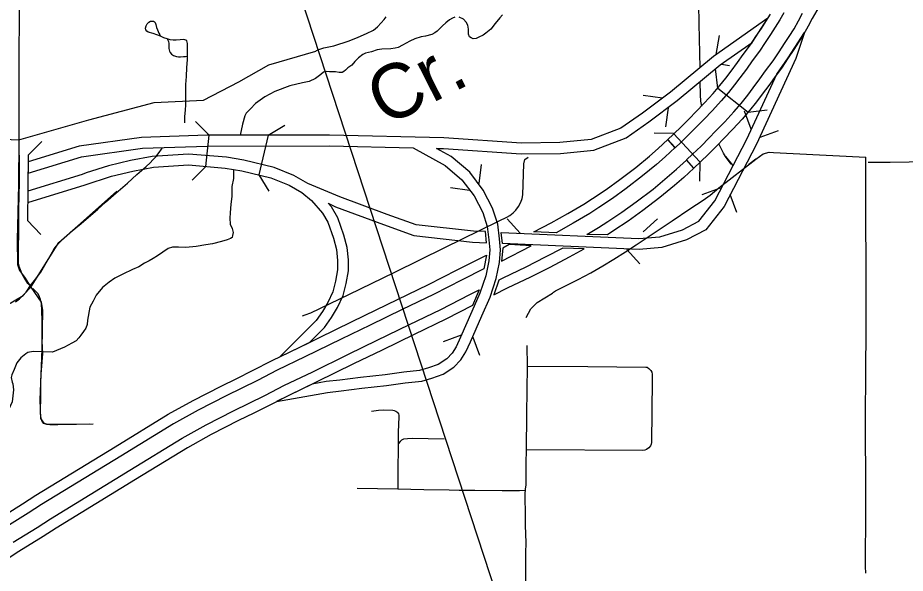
# Model space of a CAD drawing. Extents: x 670147 to 673275, y 705573 to 707613.
# Drawn here: x 671613.5 to 671751.4, y 706162.9 to 706249.1 of the extents above; entities that cross this region are included whole.
import ezdxf

# ---------------------------------------------------------------- set-up
doc = ezdxf.new("R2010")
doc.units = 0
for name, color, linetype in [('10', 7, 'Continuous'), ('19', 7, 'Continuous'), ('31', 7, 'Continuous'), ('32', 7, 'Continuous'), ('33', 7, 'Continuous'), ('34', 7, 'Continuous'), ('35', 7, 'Continuous'), ('38', 7, 'Continuous'), ('39', 7, 'Continuous'), ('45', 7, 'Continuous'), ('6', 7, 'Continuous'), ('Default', 7, 'Continuous')]:
    doc.layers.add(name, color=color, linetype=linetype)

msp = doc.modelspace()

# ---------------------------------------------------------------- linework, layer by layer
at = {"layer": '10'}
for points in [[(671727.63, 706245.26), (671730.09, 706249.03), (671721.63, 706243.12), (671714.96, 706237.58), (671710.59, 706234.32), (671707.26, 706231.99), (671702.65, 706230.22), (671697.78, 706229.73), (671691.81, 706229.67), (671679.74, 706230.49), (671661.98, 706230.9), (671642.96, 706230.88), (671632.75, 706230.55), (671623.07, 706229.18)], [(671688.83, 706214.08), (671688.66, 706215.78), (671710.05, 706214.84), (671713.29, 706215.13), (671716.82, 706216.21), (671719.35, 706217.53), (671721.86, 706220.71), (671726.83, 706230.25), (671731.47, 706240.35), (671733.25, 706242.89), (671735.79, 706246.82)], [(671735.79, 706246.82), (671734.45, 706242.81), (671728.34, 706229.51), (671723.27, 706219.79), (671720.45, 706216.2), (671717.45, 706214.65), (671713.61, 706213.47), (671710.09, 706213.15), (671688.83, 706214.08)], [(671678.62, 706228.83), (671679.66, 706228.81), (671691.76, 706227.99), (671697.87, 706228.05), (671703.04, 706228.58), (671708.06, 706230.5), (671711.57, 706232.96), (671716, 706236.26), (671722.65, 706241.79), (671727.63, 706245.26)], [(671623.07, 706229.18), (671615.15, 706226.75), (671615.13, 706224.98)], [(671623.44, 706227.53), (671632.9, 706228.88), (671642.98, 706229.2), (671661.97, 706229.22), (671674.98, 706228.92)], [(671674.98, 706228.92), (671679.92, 706226.2), (671682.54, 706223.97), (671684.43, 706221.46), (671685.77, 706218.89), (671686.48, 706216.7), (671686.71, 706214.62), (671686.87, 706213.07), (671686.71, 706211.38), (671686.26, 706209.07), (671685.35, 706206.35), (671684.08, 706203.51), (671682.33, 706199.51), (671681.66, 706198.04), (671681.03, 706197.05), (671680.21, 706196.18), (671678.86, 706195.3), (671677.34, 706194.75), (671675.97, 706194.37), (671673.51, 706194.08), (671670.64, 706193.67), (671666.78, 706193.26), (671663.56, 706192.85), (671661.44, 706192.62), (671659.29, 706192.24), (671653.73, 706189.55)], [(671653.73, 706189.55), (671661.67, 706190.95), (671663.76, 706191.19), (671666.98, 706191.6), (671670.85, 706192.01), (671673.72, 706192.42), (671676.29, 706192.72), (671677.85, 706193.15), (671679.61, 706193.78), (671681.3, 706194.89), (671682.36, 706196.01), (671683.13, 706197.24), (671683.86, 706198.82), (671685.62, 706202.83), (671686.92, 706205.74), (671687.89, 706208.64), (671688.37, 706211.13), (671688.56, 706213.07), (671688.38, 706214.8), (671688.13, 706217.05), (671687.32, 706219.55), (671685.85, 706222.36), (671683.77, 706225.13), (671680.88, 706227.59), (671678.62, 706228.83)], [(671615.13, 706224.98), (671623.44, 706227.53)], [(671658.62, 706223.39), (671656.43, 706224.63), (671653.38, 706225.88), (671648.67, 706227), (671645.97, 706227.45), (671640.08, 706227.96), (671634.39, 706227.57), (671631.04, 706226.95), (671627.65, 706226.14), (671624.14, 706225.02), (671623.51, 706224.79)], [(671624, 706223.19), (671628.1, 706224.52), (671631.39, 706225.31), (671634.6, 706225.9), (671640.07, 706226.27), (671645.76, 706225.78), (671648.34, 706225.36), (671652.86, 706224.27), (671655.7, 706223.11), (671657.66, 706222.01), (671659.19, 706220.73), (671660.9, 706218.76), (671661.72, 706217.36), (671662.59, 706214.89), (671663.06, 706213.14), (671663.22, 706211.44), (671663.23, 706209.97), (671662.92, 706208.23), (671662.51, 706206.57), (671661.72, 706204.9), (671660.9, 706203.5), (671659.89, 706202.11), (671654.24, 706196.46)], [(671623.51, 706224.79), (671615.09, 706222.21), (671615.07, 706220.44)], [(671615.07, 706220.44), (671624, 706223.19)], [(671686.38, 706214.19), (671686.23, 706215.92), (671684.32, 706215.96), (671675.43, 706216.97), (671670.92, 706218.58), (671663.58, 706221.33), (671658.62, 706223.39)], [(671654.24, 706196.46), (671658.85, 706198.7), (671661.17, 706201.02), (671662.3, 706202.58), (671663.21, 706204.12), (671664.1, 706206), (671664.56, 706207.88), (671664.91, 706209.83), (671664.9, 706211.53), (671664.72, 706213.44), (671664.19, 706215.38), (671663.25, 706218.07), (671662.27, 706219.74), (671661.75, 706220.34)], [(671661.75, 706220.34), (671662.92, 706219.78), (671670.34, 706217), (671675.05, 706215.32), (671684.19, 706214.29), (671686.38, 706214.19)]]:
    msp.add_lwpolyline(points, dxfattribs=at)
at = {"layer": '19'}
for p, q in [((671714.55, 706230.2), (671714.49, 706230.16)), ((671718.61, 706225.8), (671718.59, 706225.77))]:
    msp.add_line(p, q, dxfattribs=at)
for points in [[(671738.41, 706251.51), (671736.98, 706249), (671736.36, 706247.81), (671735.61, 706246.52), (671734.82, 706245.31), (671734.11, 706244.18), (671733.25, 706242.89), (671732.31, 706241.46), (671731.1, 706239.86), (671730.22, 706238.62), (671729.18, 706237.23), (671728.31, 706236.07), (671727.25, 706234.73), (671726.07, 706233.39), (671724.64, 706231.8), (671723.18, 706230.3), (671722.2, 706229.31), (671720.9, 706227.97), (671719.55, 706226.69), (671718.61, 706225.8)], [(671714.49, 706230.16), (671715.43, 706231.05), (671716.68, 706232.24), (671717.91, 706233.5), (671718.89, 706234.5), (671720.26, 706235.9), (671721.58, 706237.37), (671722.64, 706238.58), (671723.56, 706239.74), (671724.38, 706240.82), (671725.37, 706242.16), (671726.27, 706243.41), (671727.4, 706244.92), (671728.24, 706246.19), (671729.07, 706247.45), (671729.78, 706248.56), (671730.5, 706249.67)], [(671732.59, 706249.88), (671731.95, 706248.78), (671731.21, 706247.64), (671730.5, 706246.52), (671729.66, 706245.26), (671728.79, 706243.94), (671727.64, 706242.41), (671726.74, 706241.15), (671725.74, 706239.8), (671724.91, 706238.7), (671723.95, 706237.49), (671722.85, 706236.24), (671721.5, 706234.74), (671720.11, 706233.31), (671719.12, 706232.31), (671717.87, 706231.03), (671716.6, 706229.82), (671715.66, 706228.93), (671714.55, 706230.2)], [(671718.59, 706225.77), (671717.44, 706227.04), (671718.38, 706227.93), (671719.7, 706229.18), (671720.98, 706230.5), (671721.96, 706231.49), (671723.4, 706232.96), (671724.79, 706234.52), (671725.94, 706235.82), (671726.97, 706237.11), (671727.82, 706238.25), (671728.84, 706239.62), (671729.73, 706240.87), (671730.92, 706242.44), (671731.83, 706243.83), (671732.68, 706245.11), (671733.39, 706246.23), (671734.17, 706247.41), (671734.87, 706248.63), (671735.48, 706249.81)], [(671697.19, 706215.75), (671693.72, 706215.87), (671696.41, 706217.26), (671699, 706218.71), (671701.51, 706220.19), (671702.86, 706221.08), (671704.95, 706222.47), (671707.08, 706223.99), (671709.56, 706225.89), (671711.68, 706227.64), (671713.02, 706228.81), (671714.55, 706230.2), (671715.69, 706228.95)], [(671715.69, 706228.95), (671714.15, 706227.54), (671712.78, 706226.34), (671710.62, 706224.56), (671708.09, 706222.62), (671705.92, 706221.07), (671703.8, 706219.66), (671702.41, 706218.74), (671699.85, 706217.24), (671697.19, 706215.75)], [(671705.14, 706215.39), (671701.94, 706215.45), (671703.78, 706216.54), (671705.24, 706217.49), (671707.39, 706218.93), (671709.64, 706220.53), (671712.24, 706222.53), (671714.46, 706224.36), (671715.89, 706225.6), (671717.45, 706227.03)], [(671717.45, 706227.03), (671718.59, 706225.77), (671717.02, 706224.33), (671715.56, 706223.06), (671713.29, 706221.2), (671710.65, 706219.17), (671708.36, 706217.53), (671706.17, 706216.08), (671705.14, 706215.39)], [(671698.23, 706213.36), (671695.46, 706211.93), (671692.49, 706210.42), (671688.88, 706208.71), (671688.28, 706208.4), (671687.48, 706206.1)], [(671687.48, 706206.1), (671689.63, 706207.18), (671693.23, 706208.89), (671696.24, 706210.41), (671699.25, 706211.98), (671701.55, 706213.22), (671698.23, 706213.36)], [(671688.9, 706213.37), (671688.69, 706211.33), (671693.31, 706213.71), (671689.9, 706213.89)], [(671689.9, 706213.89), (671688.9, 706213.37)], [(671610.52, 706171.33), (671614.26, 706173.64), (671616.34, 706174.97), (671628.67, 706182.52), (671636.89, 706187.55), (671640.76, 706189.7), (671645.13, 706191.94), (671647.58, 706193.13), (671650.01, 706194.33), (671653.08, 706195.9), (671657.38, 706197.98), (671663.05, 706200.76), (671667.53, 706202.93), (671672.52, 706205.36), (671677.37, 706207.7), (671681.81, 706209.97), (671686.34, 706212.24), (671685.96, 706210.15)], [(671685.96, 706210.15), (671682.58, 706208.45), (671678.13, 706206.17), (671673.26, 706203.83), (671668.27, 706201.4), (671663.79, 706199.23), (671658.13, 706196.45), (671653.84, 706194.38), (671650.77, 706192.81), (671648.32, 706191.6), (671645.89, 706190.42), (671641.56, 706188.21), (671637.74, 706186.08), (671629.56, 706181.07), (671617.24, 706173.53), (671615.17, 706172.21), (671611.43, 706169.89)], [(671612.81, 706167.69), (671616.55, 706170), (671618.62, 706171.32), (671630.92, 706178.86), (671639.06, 706183.83), (671642.79, 706185.91), (671647.05, 706188.09), (671649.47, 706189.27), (671651.94, 706190.48), (671655, 706192.05), (671659.26, 706194.11), (671664.93, 706196.9), (671669.4, 706199.06), (671674.39, 706201.49), (671679.29, 706203.84), (671683.75, 706206.13), (671685.2, 706206.86), (671684.17, 706204.44)], [(671684.17, 706204.44), (671680.04, 706202.32), (671675.13, 706199.96), (671670.14, 706197.53), (671665.68, 706195.37), (671660.01, 706192.59), (671655.76, 706190.53), (671652.7, 706188.97), (671650.21, 706187.74), (671647.81, 706186.57), (671643.59, 706184.41), (671639.91, 706182.36), (671631.8, 706177.41), (671619.52, 706169.88), (671617.46, 706168.57), (671613.72, 706166.25), (671610.72, 706164.34)]]:
    msp.add_lwpolyline(points, dxfattribs=at)
at = {"layer": '31'}
for points in [[(671657.78, 706202.83), (671658.2, 706202.99), (671659.05, 706203.28), (671664.98, 706206.17), (671672.14, 706209.63), (671679.88, 706213.45), (671685.28, 706216.08), (671688.31, 706217.57), (671689.54, 706218.15), (671690.01, 706218.44), (671690.53, 706218.84), (671690.9, 706219.24), (671691.34, 706219.79), (671691.7, 706220.48), (671691.89, 706221.06), (671691.99, 706221.65), (671692.15, 706226.44), (671692.31, 706227.1), (671692.85, 706227.49)], [(671723.5, 706227.56), (671724.59, 706226.24)]]:
    msp.add_lwpolyline(points, dxfattribs=at)
at = {"layer": '32'}
for points in [[(671613.67, 706230.15), (671613.74, 706225.48), (671613.76, 706223.62), (671613.68, 706221.39), (671613.64, 706219.53), (671613.62, 706216.22), (671613.61, 706212.87), (671613.59, 706211.03), (671613.67, 706210.55), (671613.9, 706210.01), (671614.16, 706209.37), (671614.63, 706208.51), (671614.98, 706207.98), (671615.5, 706207.54)], [(671615.5, 706207.54), (671616.14, 706208.3), (671616.67, 706208.99), (671617.11, 706209.62), (671617.73, 706210.71), (671618.49, 706212.04), (671618.91, 706212.8), (671619.19, 706213.26), (671619.52, 706213.66), (671620.05, 706214.29), (671620.49, 706214.71), (671620.93, 706215.09), (671621.74, 706215.81), (671623.37, 706217.18), (671625.95, 706219.38), (671627.14, 706220.51), (671628.38, 706221.55), (671630.6, 706223.46), (671632.02, 706224.76), (671632.76, 706225.41), (671633.46, 706226.03), (671634.1, 706226.6), (671634.54, 706227.06), (671634.96, 706227.54), (671635.5, 706228.19), (671635.84, 706228.7), (671636.02, 706228.93)], [(671613.18, 706205.01), (671613.78, 706205.47), (671614.31, 706206.02), (671614.81, 706206.53), (671615.5, 706207.54)]]:
    msp.add_lwpolyline(points, dxfattribs=at)
at = {"layer": '33'}
for points in [[(671614.61, 706335.87), (671614.53, 706329.13), (671614.47, 706320.89), (671614.35, 706312.7), (671614.26, 706305.93), (671614.22, 706299.44), (671614.1, 706290.42), (671614.06, 706283.16), (671614.03, 706277.49), (671613.97, 706271.15), (671613.85, 706261.98), (671613.77, 706252.69), (671613.68, 706239.92), (671613.68, 706230.44), (671613.67, 706230.15)], [(671719.06, 706281.88), (671719.22, 706281.25), (671719.37, 706280.51), (671719.38, 706279.99), (671719.25, 706277.24), (671719.23, 706271.14), (671719.2, 706264.43), (671719.23, 706261.89), (671719.22, 706259.04), (671719.25, 706254.43), (671719.37, 706248.16), (671719.49, 706241.35)], [(671613.67, 706230.15), (671624.58, 706233.28), (671634.73, 706235.95), (671642.39, 706236.3), (671647.9, 706239.15), (671652.53, 706241.82), (671659.82, 706243.93)], [(671719.53, 706239.19), (671719.57, 706237.13), (671719.62, 706236.17), (671719.75, 706235.38)], [(671542.03, 706230.44), (671542.38, 706230.63), (671542.62, 706230.72), (671543.01, 706230.77), (671543.48, 706230.82), (671544.19, 706230.84), (671545.68, 706230.84), (671550.29, 706230.76), (671554.88, 706230.77), (671559.51, 706230.82), (671561.24, 706230.82), (671564.77, 706230.82), (671569, 706230.82), (671571.4, 706230.76), (671574.3, 706230.75), (671578.61, 706230.72), (671582.19, 706230.67), (671588.77, 706230.65), (671591.88, 706230.59), (671599.43, 706230.52), (671610.14, 706230.3), (671613.67, 706230.15)], [(671613.67, 706230.15), (671613.66, 706223.17), (671613.46, 706214.65), (671613.51, 706210.82), (671613.79, 706209.89), (671614.55, 706208.82), (671615.56, 706207.31)], [(671724.4, 706226.4), (671723.5, 706227.56), (671723.19, 706228.08), (671722.44, 706229.55)], [(671692.55, 706202.58), (671693.23, 706203.9), (671694.23, 706204.92), (671696.61, 706206.37), (671696.79, 706206.52), (671697.06, 706206.7), (671697.72, 706207.05), (671699.04, 706207.68), (671700.62, 706208.5), (671702.58, 706209.51), (671704.43, 706210.6), (671706.16, 706211.65), (671707.94, 706212.77), (671709.63, 706213.85), (671711.93, 706215.43), (671715.2, 706217.61), (671717.96, 706219.45), (671720.01, 706220.81), (671721.11, 706221.56), (671722.47, 706222.71), (671728.24, 706227.16)], [(671728.24, 706227.16), (671727.15, 706226.34)], [(671728.24, 706227.16), (671729.33, 706227.98), (671730.29, 706228.25), (671730.96, 706228.21), (671734.03, 706228.03), (671745.32, 706227.47)], [(671745.32, 706162.87), (671745.29, 706163.19), (671745.24, 706163.61), (671745.23, 706164.09), (671745.26, 706165.15), (671745.28, 706166.64), (671745.32, 706170.06), (671745.32, 706174.86), (671745.28, 706187.31), (671745.29, 706193.75), (671745.37, 706201.14), (671745.32, 706227.47)], [(671611.58, 706204.33), (671614.39, 706206.01), (671615.68, 706207.44), (671619.91, 706214.25), (671622.87, 706216.81), (671628.91, 706222.2)], [(671691.57, 706122.65), (671692.4, 706153.43), (671692.42, 706154.32), (671692.41, 706156.63), (671692.45, 706162.75), (671692.49, 706165.97), (671692.51, 706167.65), (671692.44, 706170.27), (671692.42, 706172.2), (671692.37, 706174.58), (671692.36, 706175.02), (671692.37, 706175.35), (671692.4, 706175.71), (671692.43, 706175.95), (671692.48, 706176.3), (671692.51, 706176.54), (671692.53, 706179.95), (671692.57, 706182.04), (671692.64, 706187.59), (671692.75, 706195.04), (671692.68, 706198.24)], [(671692.75, 706195.04), (671702.12, 706194.97), (671711.13, 706194.89), (671711.32, 706194.85), (671711.61, 706194.67), (671711.89, 706194.37), (671712.03, 706194.09), (671712.09, 706193.8), (671712.1, 706192.86), (671712.02, 706183.19), (671711.97, 706182.92), (671711.86, 706182.66), (671711.59, 706182.32), (671711.23, 706182.07), (671710.95, 706181.96), (671710.65, 706181.91), (671692.57, 706182.04)], [(671679.81, 706183.69), (671674.82, 706183.78), (671674.08, 706183.75), (671673.47, 706183.69), (671673.17, 706183.51), (671672.95, 706183.32), (671672.66, 706182.98)], [(671692.4, 706175.71), (671691.51, 706175.69), (671688.8, 706175.69), (671684.56, 706175.71), (671682.13, 706175.73), (671680.57, 706175.77), (671676.61, 706175.83), (671672.61, 706175.92), (671666.27, 706176.05)]]:
    msp.add_lwpolyline(points, dxfattribs=at)
at = {"layer": '34'}
for points in [[(671659.82, 706243.93), (671659.94, 706244.02), (671660.46, 706244.25), (671661.08, 706244.44), (671662.64, 706244.77), (671665.02, 706245.52), (671666.43, 706246.09), (671667.72, 706246.65), (671668.8, 706247.2), (671669.43, 706247.72), (671670.02, 706248.33), (671670.48, 706248.86), (671670.76, 706249.28)], [(671635.72, 706246.25), (671634.55, 706246.65), (671633.78, 706246.9), (671633.56, 706247.05), (671633.41, 706247.25), (671633.4, 706247.51), (671633.46, 706247.86), (671633.63, 706248.19), (671633.91, 706248.45), (671634.14, 706248.59), (671634.32, 706248.61), (671634.61, 706248.57), (671634.76, 706248.51), (671634.88, 706248.38), (671634.98, 706248.07), (671635.09, 706247.59), (671635.25, 706247.23), (671635.47, 706246.74), (671635.62, 706246.48), (671635.72, 706246.25)], [(671639.48, 706232.79), (671639.49, 706233.11), (671639.5, 706233.73), (671639.57, 706234.81), (671639.62, 706235.53), (671639.66, 706236.31), (671639.65, 706236.84), (671639.62, 706237.62), (671639.63, 706238.13), (671639.64, 706238.78), (671639.73, 706239.98), (671639.82, 706241.39), (671639.9, 706242.61), (671639.92, 706243.15), (671639.91, 706245.1), (671639.87, 706245.35), (671639.79, 706245.51), (671639.64, 706245.63), (671639.49, 706245.71), (671639.26, 706245.73), (671638.77, 706245.7), (671638.16, 706245.65), (671637.68, 706245.66), (671637.22, 706245.71), (671636.73, 706245.84), (671636.24, 706246.02), (671635.72, 706246.25)], [(671636.73, 706245.84), (671636.85, 706245.63), (671636.93, 706245.41), (671636.98, 706245.14), (671637.02, 706244.33), (671637.11, 706243.91), (671637.21, 706243.7), (671637.4, 706243.48), (671637.74, 706243.27), (671638.19, 706243.09), (671638.51, 706243.04), (671638.83, 706243.05), (671639.3, 706243.09), (671639.58, 706243.12), (671639.92, 706243.15)], [(671615.56, 706207.31), (671617.18, 706204.95), (671617.38, 706203.71), (671617.28, 706197.65), (671616.98, 706189.8), (671617.08, 706186.89), (671617.57, 706186.15), (671618.16, 706186.01), (671624.72, 706186.06)], [(671668.51, 706188.05), (671669.59, 706188.21), (671670.36, 706188.24), (671671.8, 706188.19), (671672.04, 706188.14), (671672.26, 706188.05), (671672.44, 706187.93), (671672.6, 706187.78), (671672.68, 706187.62), (671672.73, 706187.43), (671672.74, 706187.17), (671672.64, 706184.77), (671672.66, 706182.98), (671672.61, 706178.41), (671672.57, 706176.95), (671672.59, 706176.17), (671672.61, 706175.92)]]:
    msp.add_lwpolyline(points, dxfattribs=at)
at = {"layer": '35'}
for points in [[(671681.46, 706249.2), (671681.09, 706249.07), (671680.61, 706248.78), (671680.04, 706248.35), (671679.52, 706247.84), (671679.18, 706247.5), (671678.72, 706247.05), (671678.32, 706246.78), (671677.89, 706246.52)], [(671688.87, 706249.57), (671688.44, 706249.1), (671687.7, 706248.23), (671687.03, 706247.36), (671686.27, 706246.72), (671685.83, 706246.42), (671685.15, 706246.08), (671684.78, 706245.92), (671684.29, 706245.87), (671683.98, 706245.98), (671683.7, 706246.18), (671683.58, 706246.55), (671683.55, 706247.36), (671683.48, 706247.95), (671683.23, 706248.41), (671682.77, 706248.91), (671682.14, 706249.21)], [(671677.89, 706246.52), (671676.86, 706246.26), (671676.2, 706246.14), (671675.23, 706245.84), (671674.43, 706245.47), (671673.33, 706244.85), (671672.63, 706244.52), (671672.15, 706244.38), (671671.49, 706244.3), (671670.1, 706244.25), (671669.38, 706244.16), (671668.5, 706243.85), (671667.55, 706243.62), (671667.16, 706243.39), (671666.49, 706242.89), (671665.89, 706242.31), (671665.43, 706241.78), (671664.82, 706241.34), (671664.47, 706240.99), (671664.22, 706240.79), (671663.93, 706240.63), (671663.48, 706240.62), (671662.88, 706240.73), (671662.53, 706240.71), (671661.99, 706240.73), (671661.57, 706240.79), (671661.06, 706240.68), (671660.63, 706240.3), (671659.77, 706239.71)], [(671659.77, 706239.71), (671658.81, 706239.2), (671657.75, 706239.02), (671655.79, 706238.56), (671653.46, 706237.69), (671651.92, 706236.84), (671650.45, 706235.81), (671649.71, 706234.96), (671649.04, 706234.32), (671648.79, 706233.91), (671648.46, 706232.59), (671648.1, 706230.91)], [(671647.07, 706225.5), (671647.03, 706225.25), (671647.03, 706224.17), (671646.78, 706222.9), (671646.77, 706221.38), (671646.65, 706220.2), (671646.54, 706218.85), (671646.47, 706217.99), (671646.54, 706217.08), (671646.83, 706216.4), (671647, 706215.8), (671646.92, 706215.33), (671646.82, 706215.02), (671646.58, 706214.84), (671646.09, 706214.62), (671645.17, 706214.39), (671643.81, 706214.04), (671642.74, 706213.84), (671641.25, 706213.58), (671639.66, 706213.45), (671638.48, 706213.5), (671637.59, 706213.49), (671636.91, 706213.29), (671636.07, 706212.71), (671635.26, 706212.13), (671634.59, 706211.75), (671633.94, 706211.38), (671633.21, 706210.99), (671632.32, 706210.43), (671631.34, 706210.03), (671629.84, 706209.3), (671628.6, 706208.67), (671627.72, 706208.09), (671626.7, 706207.22), (671625.73, 706206.04), (671625.22, 706205.14), (671624.75, 706204.16), (671624.35, 706202.17)], [(671624.35, 706202.17), (671624.29, 706201.5), (671624.09, 706200.91), (671623.74, 706200.41), (671623.32, 706199.84), (671623.02, 706199.4), (671622.6, 706198.94), (671621.94, 706198.57), (671620.78, 706197.98), (671618.92, 706197.19), (671615.92, 706197.31)], [(671615.92, 706197.31), (671615.11, 706197.16), (671614.76, 706196.94), (671614.01, 706196.33), (671613.39, 706195.52), (671612.98, 706194.49), (671612.59, 706193.7), (671612.5, 706193.24), (671612.65, 706192.54), (671612.74, 706192.3), (671612.89, 706191.37), (671612.65, 706189.5), (671612.14, 706188.34), (671611.83, 706187.86)]]:
    msp.add_lwpolyline(points, dxfattribs=at)
at = {"layer": '38'}
for points in [[(671722.06, 706243.41), (671722.58, 706246.37)], [(671724.14, 706241.65), (671722.89, 706241.87)], [(671710.73, 706237.12), (671713.7, 706236.71)], [(671714.61, 706235.15), (671714.2, 706232.18)], [(671727.47, 706231.8), (671726.43, 706234.61)], [(671731.66, 706231.56), (671728.85, 706230.52)], [(671617.29, 706229.88), (671615.16, 706227.76)], [(671685.56, 706226.36), (671685.15, 706223.39)], [(671683.74, 706222.32), (671680.77, 706222.73)], [(671722.66, 706222.65), (671719.84, 706221.61)], [(671725.28, 706218.86), (671724.23, 706221.67)], [(671615.03, 706217.65), (671617.1, 706215.48)], [(671689.57, 706217.9), (671691.6, 706215.69)], [(671710.72, 706215.87), (671712.95, 706217.89)], [(671708.17, 706213.12), (671710.2, 706210.91)], [(671679.66, 706198.84), (671682.47, 706199.89)], [(671684.22, 706199.55), (671685.28, 706196.74)]]:
    msp.add_lwpolyline(points, dxfattribs=at)
at = {"layer": '39'}
for p, q in [((671722.3, 706238.19), (671721.95, 706241.17)), ((671722.3, 706238.19), (671727, 706234.46)), ((671727, 706234.46), (671729.98, 706234.81)), ((671643.27, 706230.88), (671641.14, 706233)), ((671652.46, 706230.89), (671655.02, 706232.46)), ((671715.4, 706231.13), (671712.4, 706231.21)), ((671642.77, 706226.04), (671643.27, 706230.88)), ((671652.46, 706230.89), (671650.99, 706224.72)), ((671719.52, 706226.77), (671715.4, 706231.13)), ((671615.16, 706227.76), (671615.03, 706217.65)), ((671642.77, 706226.04), (671640.65, 706223.92)), ((671719.52, 706226.77), (671719.44, 706223.77)), ((671650.99, 706224.72), (671652.56, 706222.17))]:
    msp.add_line(p, q, dxfattribs=at)
at = {"layer": '45'}
msp.add_lwpolyline([(671625.24, 706186.03), (671622.64, 706185.96), (671619.75, 706185.9), (671618.5, 706185.92), (671618.04, 706185.96), (671617.6, 706186.1), (671617.34, 706186.43), (671617.14, 706186.91), (671617.07, 706187.69), (671617.12, 706190.56), (671617.1, 706192.64), (671617.18, 706193.78), (671617.25, 706195), (671617.36, 706196.36), (671617.4, 706196.93), (671617.36, 706197.92), (671617.31, 706198.88), (671617.32, 706200.91), (671617.32, 706202.07), (671617.27, 706203.63), (671617.2, 706204.76), (671617.08, 706205.38), (671616.92, 706205.8), (671616.68, 706206.25), (671616.31, 706206.67), (671615.89, 706207.1)], dxfattribs=at)
at = {"layer": '6'}
msp.add_lwpolyline([(671771.54, 706226.93), (671765.06, 706226.85), (671762.29, 706226.82), (671754.99, 706226.74), (671749.08, 706226.67), (671745.8, 706226.63), (671745.65, 706226.63)], dxfattribs=at)
at = {"layer": 'Default'}
msp.add_line((671630.23, 706335.38), (671790.91, 705845.78), dxfattribs=at)

# ---------------------------------------------------------------- texts
at = {"layer": '35'}
msp.add_text('Cr.', height=8.448, rotation=26.8426, dxfattribs=at).set_placement((671670.6, 706232.13))

doc.saveas('drawing.dxf')
